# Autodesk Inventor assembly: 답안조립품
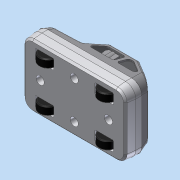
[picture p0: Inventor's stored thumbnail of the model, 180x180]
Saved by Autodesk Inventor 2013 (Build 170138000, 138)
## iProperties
Created: 2015-05
Part Number: 답안조립품
Document SubType Name: Assembly
Designer: Administrator
Author: Administrator
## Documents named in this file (7)
- C:\Users\Administrator\Desktop\450508V1046\답안조립품.iam
- C:\Users\Administrator\Desktop\450508V1046\본체.ipt
- C:\Users\Administrator\Desktop\450508V1046\M2x4.ipt
- C:\Users\Administrator\Desktop\450508V1046\M4x10.ipt
- C:\Users\Administrator\Desktop\450508V1046\바퀴.ipt
- C:\Users\Administrator\Desktop\450508V1046\바퀴고정부.ipt
- C:\Users\Administrator\Desktop\450508V1046\커버.ipt
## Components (20 placed, 2 different names)
1. M2x4:1
2. M4x10:1
3. M2x4:2
4. M2x4:3
5. M2x4:4
6. M2x4:5
7. M2x4:6
8. M2x4:7
9. M2x4:8
10. M2x4:9
11. M2x4:10
12. M2x4:11
13. M2x4:12
14. M2x4:13
15. M2x4:14
16. M2x4:15
17. M2x4:16
18. M4x10:2
19. M4x10:3
20. M4x10:4
